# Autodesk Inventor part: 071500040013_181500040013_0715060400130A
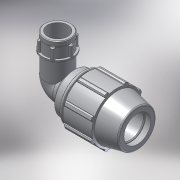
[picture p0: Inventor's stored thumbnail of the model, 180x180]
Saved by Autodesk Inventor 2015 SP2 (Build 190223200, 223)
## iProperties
Created: 2017-02
Part Number: 071500040013_181500040013_0715060400130A
Material: PVC-Piping
Description: PLASSON 90° ELBOW FEMALE ADAPTOR 40-1.1/4"
Document SubType Name: Modeling
Designer: KIM
Mass: 92.6774 g
Surface Area: 199.44 cm^2
Volume: 66.1981 cm^3
Density: 1.4 g/cm^3
Appearance: Smooth - White
Author: KIM
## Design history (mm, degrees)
derived "07150.ipt"
feature "Solid1::07150.ipt"
tag "TaggingFeature1"
body "Solid1"
other parameters: "d4" = 9.91667, "d5" = 29.75, "d7" = 82, "d9" = 17, "d11" = 3.96667, "d13" = 120 deg, "d14" = 56, "d15" = 12 deg, "d16" = 71.34, "d18" = 2, "d19" = 35 deg, "d20" = 17.5 deg, "d21" = 76.26, "d23" = 0, "d25" = 360 deg, "d27" = 1.64, "d33" = 0.8, "d42" = 44.03, "d43" = 2.46, "d46" = 1.2, "d51" = 119, "d68" = 3.96667, "d72" = 62, "d73" = 50.6376, "d74" = 25, "d75" = 58.23324, "d76" = 38.952, "d77" = 27.5, "d79" = 15.5808, "d80" = 1.16856, "d83" = 0, "d84" = 0, "d91" = 61.5, "d93" = 84, "d94" = 38.952, "d95" = 27.2664, "d96" = 11.9, "d97" = 50 deg, "d98" = 35.0568, "d99" = 0.5, "d100" = 0.5, "d101" = 8.33333, "d102" = 50.6376, "d103" = 21.25, "d104" = 0, "d108" = 360 deg, "d110" = 1.51913, "E_" = 82, "A_" = 119, "l_" = 84, "l_2" = 25, "A_1" = 62, "Rp_" = 38.952, "d105" = 7.59564
